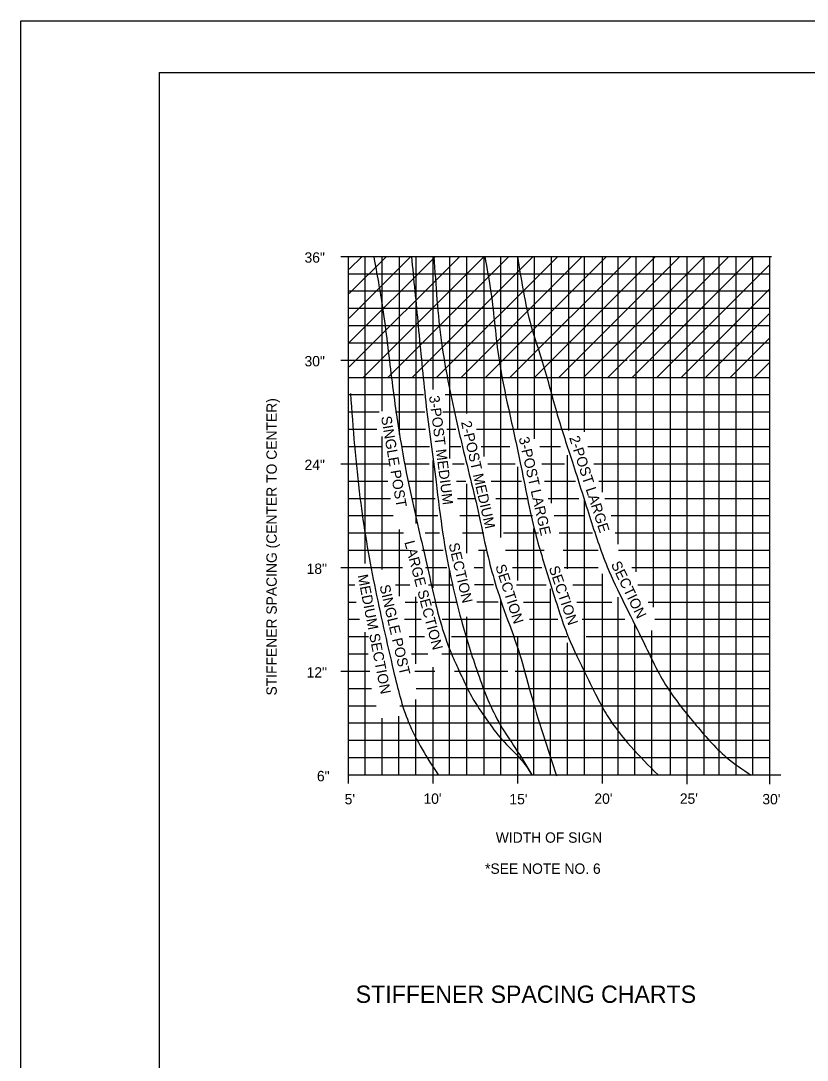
# Model space of a CAD drawing. Extents: x 650495 to 652241, y 298458 to 299646.
# Drawn here: x 650495.3 to 650722.7, y 299344.9 to 299645.6 of the extents above; entities that cross this region are included whole.
import ezdxf

# ---------------------------------------------------------------- set-up
doc = ezdxf.new("R2010")
doc.units = 0
for name, color, linetype in [('1', 7, 'Continuous'), ('2', 7, 'Continuous'), ('3', 7, 'Continuous'), ('PLT-BNDY', 7, 'Continuous')]:
    doc.layers.add(name, color=color, linetype=linetype)

msp = doc.modelspace()

# ---------------------------------------------------------------- linework, layer by layer
at = {"layer": '1'}
for q in [(651321.31, 299630.63), (650535.31, 299066.63)]:
    msp.add_line((650535.31, 299630.63), q, dxfattribs=at)
at = {"layer": '2'}
for p, q in [((650587.82, 299577.45), (650712.44, 299577.45)), ((650590.32, 299573.76), (650594, 299577.45)), ((650590.32, 299566.69), (650601.07, 299577.45)), ((650590.32, 299559.62), (650608.15, 299577.45)), ((650590.32, 299552.55), (650615.22, 299577.45)), ((650590.32, 299545.48), (650622.29, 299577.45)), ((650593.07, 299577.45), (650593.07, 299577.45)), ((650594.36, 299542.45), (650629.36, 299577.45)), ((650601.43, 299542.45), (650636.43, 299577.45)), ((650605.32, 299577.45), (650605.32, 299577.45)), ((650608.5, 299542.45), (650643.5, 299577.45)), ((650615.57, 299542.45), (650650.57, 299577.45)), ((650622.64, 299542.45), (650657.64, 299577.45)), ((650623.69, 299577.45), (650623.69, 299577.45)), ((650629.07, 299577.45), (650629.07, 299577.45)), ((650629.71, 299542.45), (650664.71, 299577.45)), ((650636.78, 299542.45), (650671.78, 299577.45)), ((650643.86, 299542.45), (650678.86, 299577.45)), ((650650.93, 299542.45), (650685.93, 299577.45)), ((650658, 299542.45), (650693, 299577.45)), ((650658.94, 299577.45), (650658.94, 299577.45)), ((650665.07, 299542.45), (650700.07, 299577.45)), ((650672.14, 299542.45), (650707.14, 299577.45)), ((650679.21, 299542.45), (650711.82, 299575.05)), ((650590.32, 299572.45), (650711.82, 299572.45)), ((650605.32, 299572.45), (650605.32, 299572.45)), ((650630.32, 299569.82), (650630.32, 299569.82)), ((650590.32, 299567.45), (650711.82, 299567.45)), ((650686.28, 299542.45), (650711.82, 299567.98)), ((650590.32, 299562.45), (650711.82, 299562.45)), ((650631.44, 299562.45), (650631.44, 299562.45)), ((650693.35, 299542.45), (650711.82, 299560.91)), ((650590.32, 299557.45), (650711.82, 299557.45)), ((650625.32, 299557.45), (650625.32, 299557.45)), ((650662.94, 299557.45), (650662.94, 299557.45)), ((650700.42, 299542.45), (650711.82, 299553.84)), ((650590.32, 299552.45), (650711.82, 299552.45)), ((650587.82, 299547.45), (650670.69, 299547.45)), ((650595.32, 299547.45), (650595.32, 299547.45)), ((650634.57, 299547.45), (650634.57, 299547.45)), ((650671.32, 299547.45), (650711.82, 299547.45)), ((650707.5, 299542.45), (650711.82, 299546.77)), ((650590.32, 299542.45), (650711.82, 299542.45)), ((650607.69, 299542.45), (650607.69, 299542.45)), ((650590.32, 299537.45), (650611.73, 299537.45)), ((650618.07, 299537.45), (650711.82, 299537.45)), ((650590.32, 299532.45), (650598.94, 299532.45)), ((650603.69, 299532.45), (650612.12, 299532.45)), ((650617.38, 299532.45), (650711.82, 299532.45)), ((650590.32, 299527.45), (650598.25, 299527.45)), ((650604.69, 299527.45), (650612.32, 299527.45)), ((650610.32, 299527.45), (650610.32, 299527.45)), ((650618.56, 299527.45), (650621.14, 299527.45)), ((650627.09, 299527.45), (650711.82, 299527.45)), ((650590.32, 299522.45), (650599.64, 299522.45)), ((650605.57, 299522.45), (650613.51, 299522.45)), ((650619.46, 299522.45), (650622.53, 299522.45)), ((650628.47, 299522.45), (650636.69, 299522.45)), ((650645.41, 299522.45), (650651.36, 299522.45)), ((650659.28, 299522.45), (650711.82, 299522.45)), ((650587.82, 299517.45), (650601.94, 299517.45)), ((650606.57, 299517.45), (650613.41, 299517.45)), ((650620.15, 299517.45), (650623.52, 299517.45)), ((650630.35, 299517.45), (650638.32, 299517.45)), ((650646.01, 299517.45), (650652.55, 299517.45)), ((650661.07, 299517.45), (650711.82, 299517.45)), ((650590.32, 299512.45), (650601.42, 299512.45)), ((650607.44, 299512.45), (650614.44, 299512.45)), ((650621.34, 299512.45), (650624.01, 299512.45)), ((650631.35, 299512.45), (650640.07, 299512.45)), ((650645.32, 299512.45), (650645.32, 299512.45)), ((650646.8, 299512.45), (650655.72, 299512.45)), ((650662.46, 299512.45), (650711.82, 299512.45)), ((650590.32, 299507.45), (650602.22, 299507.45)), ((650608.44, 299507.45), (650615.1, 299507.45)), ((650621.64, 299507.45), (650626.59, 299507.45)), ((650632.73, 299507.45), (650641.69, 299507.45)), ((650647.79, 299507.45), (650656.71, 299507.45)), ((650664.24, 299507.45), (650711.82, 299507.45)), ((650590.32, 299502.45), (650603.01, 299502.45)), ((650609.44, 299502.45), (650615.89, 299502.45)), ((650622.23, 299502.45), (650627.78, 299502.45)), ((650633.92, 299502.45), (650643.32, 299502.45)), ((650649.58, 299502.45), (650658.1, 299502.45)), ((650666.02, 299502.45), (650711.82, 299502.45)), ((650590.32, 299497.45), (650605.94, 299497.45)), ((650612.22, 299497.45), (650616.39, 299497.45)), ((650623.02, 299497.45), (650629.17, 299497.45)), ((650634.91, 299497.45), (650645.07, 299497.45)), ((650650.96, 299497.45), (650660.67, 299497.45)), ((650667.21, 299497.45), (650711.82, 299497.45)), ((650590.32, 299492.45), (650606.94, 299492.45)), ((650605.32, 299492.45), (650605.32, 299492.45)), ((650611.32, 299492.45), (650617.47, 299492.45)), ((650627.69, 299492.45), (650630.16, 299492.45)), ((650635.51, 299492.45), (650646.69, 299492.45)), ((650652.15, 299492.45), (650662.26, 299492.45)), ((650668.2, 299492.45), (650711.82, 299492.45)), ((650587.82, 299487.45), (650605.68, 299487.45)), ((650590.32, 299487.45), (650590.32, 299487.45)), ((650612.32, 299487.45), (650618.47, 299487.45)), ((650626.39, 299487.45), (650628.97, 299487.45)), ((650637.49, 299487.45), (650646.01, 299487.45)), ((650646.57, 299487.45), (650646.57, 299487.45)), ((650652.44, 299487.45), (650662.26, 299487.45)), ((650671.97, 299487.45), (650711.82, 299487.45)), ((650590.32, 299482.45), (650591.91, 299482.45)), ((650603.7, 299482.45), (650607.86, 299482.45)), ((650613.19, 299482.45), (650620.15, 299482.45)), ((650632.04, 299482.45), (650626.49, 299482.45)), ((650638.68, 299482.45), (650647.2, 299482.45)), ((650654.93, 299482.45), (650663.64, 299482.45)), ((650673.75, 299482.45), (650711.82, 299482.45)), ((650590.32, 299477.45), (650592.31, 299477.45)), ((650606.48, 299477.45), (650610.07, 299477.45)), ((650614.19, 299477.45), (650621.54, 299477.45)), ((650633.33, 299477.45), (650627.18, 299477.45)), ((650640.66, 299477.45), (650648.39, 299477.45)), ((650656.11, 299477.45), (650666.22, 299477.45)), ((650676.72, 299477.45), (650711.82, 299477.45)), ((650590.32, 299472.45), (650593.3, 299472.45)), ((650606.28, 299472.45), (650611.07, 299472.45)), ((650617.18, 299472.45), (650633.72, 299472.45)), ((650642.44, 299472.45), (650650.57, 299472.45)), ((650657.7, 299472.45), (650669.99, 299472.45)), ((650678.7, 299472.45), (650711.82, 299472.45)), ((650706.69, 299472.45), (650706.69, 299472.45)), ((650590.32, 299467.45), (650595.82, 299467.45)), ((650607.67, 299467.45), (650612.07, 299467.45)), ((650610.32, 299467.45), (650610.32, 299467.45)), ((650619.85, 299467.45), (650653.24, 299467.45)), ((650657.69, 299467.45), (650657.69, 299467.45)), ((650658.79, 299467.45), (650711.82, 299467.45)), ((650590.32, 299462.45), (650595.78, 299462.45)), ((650608.26, 299462.45), (650613.07, 299462.45)), ((650617.07, 299462.45), (650711.82, 299462.45)), ((650587.82, 299457.45), (650596.27, 299457.45)), ((650595.32, 299457.45), (650595.32, 299457.45)), ((650609.25, 299457.45), (650615, 299457.45)), ((650620.74, 299457.45), (650636.19, 299457.45)), ((650638.32, 299457.45), (650711.82, 299457.45)), ((650590.32, 299452.45), (650596.77, 299452.45)), ((650609.65, 299452.45), (650711.82, 299452.45)), ((650590.32, 299447.45), (650598.06, 299447.45)), ((650604.94, 299447.45), (650711.82, 299447.45)), ((650640.32, 299447.45), (650640.32, 299447.45)), ((650684.57, 299447.45), (650684.57, 299447.45)), ((650590.32, 299442.45), (650711.82, 299442.45)), ((650690.32, 299442.45), (650690.32, 299442.45)), ((650590.32, 299437.45), (650711.82, 299437.45)), ((650625.32, 299437.45), (650625.32, 299437.45)), ((650647.94, 299437.45), (650647.94, 299437.45)), ((650685.32, 299437.45), (650685.32, 299437.45)), ((650697.69, 299437.45), (650697.69, 299437.45)), ((650590.32, 299432.45), (650711.82, 299432.45)), ((650605.32, 299432.45), (650605.32, 299432.45)), ((650589.94, 299427.45), (650715.07, 299427.45)), ((650710.32, 299427.45), (650710.32, 299427.45))]:
    msp.add_line(p, q, dxfattribs=at)
for points in [[(650589.94, 299577.45), (650589.94, 299424.95)], [(650594.82, 299577.45), (650594.82, 299488.57)], [(650599.69, 299577.45), (650599.69, 299532.7)], [(650604.69, 299577.45), (650604.69, 299525.95)], [(650609.57, 299577.45), (650609.57, 299500.2)], [(650614.44, 299577.45), (650614.44, 299538.95)], [(650619.32, 299577.45), (650619.32, 299518.93)], [(650624.19, 299577.45), (650624.19, 299532.01)], [(650629.19, 299577.45), (650629.19, 299519.52)], [(650634.07, 299577.45), (650634.07, 299496.14)], [(650638.94, 299577.45), (650638.94, 299527.32)], [(650643.82, 299577.45), (650643.82, 299524.68)], [(650648.69, 299577.45), (650648.69, 299506.05)], [(650653.69, 299577.45), (650653.69, 299527.06)], [(650658.19, 299577.45), (650658.19, 299526.66)], [(650663.44, 299577.45), (650663.44, 299509.22)], [(650667.94, 299577.45), (650667.94, 299494.15)], [(650673.19, 299577.45), (650673.19, 299486.23)], [(650678.19, 299577.45), (650678.19, 299475.92)], [(650683.07, 299577.45), (650683.07, 299427.45)], [(650687.94, 299577.45), (650687.94, 299424.77)], [(650692.82, 299577.45), (650692.82, 299427.45)], [(650697.19, 299577.45), (650697.19, 299427.45)], [(650702.07, 299577.45), (650702.07, 299427.45)], [(650706.94, 299577.45), (650706.94, 299427.45)], [(650711.82, 299577.45), (650711.82, 299424.74)], [(650599.69, 299525.37), (650599.69, 299486.82)], [(650614.44, 299518.43), (650614.44, 299481.57)], [(650653.32, 299519.92), (650653.32, 299487.02)], [(650638.94, 299516.57), (650638.94, 299483.65)], [(650624.19, 299511.6), (650624.19, 299491.58)], [(650658.19, 299507.43), (650658.19, 299427.45)], [(650604.69, 299498.42), (650604.69, 299479.19)], [(650643.57, 299498.71), (650643.57, 299427.45)], [(650629.19, 299492.57), (650629.19, 299427.45)], [(650619.19, 299487.02), (650619.19, 299427.45)], [(650663.44, 299485.63), (650663.44, 299424.95)], [(650648.44, 299481.27), (650648.44, 299427.45)], [(650609.44, 299478.95), (650609.44, 299459.57)], [(650634.07, 299477.9), (650634.07, 299427.45)], [(650667.94, 299478.89), (650667.94, 299427.45)], [(650624.19, 299473.14), (650624.19, 299427.45)], [(650672.82, 299470.96), (650672.82, 299427.45)], [(650677.69, 299469.18), (650677.69, 299427.45)], [(650594.82, 299468.69), (650594.82, 299427.45)], [(650638.94, 299467.6), (650638.94, 299424.95)], [(650653.32, 299465.61), (650653.32, 299427.45)], [(650614.44, 299458.58), (650614.44, 299424.95)], [(650609.44, 299449.26), (650609.44, 299427.45)], [(650599.69, 299443.81), (650599.69, 299427.45)], [(650604.57, 299444.41), (650604.57, 299427.45)]]:
    msp.add_lwpolyline(points, dxfattribs=at)
for points in [[(650597.36, 299577.45), (650599.94, 299562.53), (650602.51, 299542.32), (650605.49, 299522.1), (650608.26, 299507.83), (650610.64, 299497.33), (650613.02, 299487.02), (650615.2, 299477.31), (650616.58, 299471.96), (650619.95, 299462.24), (650621.93, 299457.88), (650624.31, 299452.73), (650627.09, 299447.78), (650630.06, 299443.41), (650634.42, 299437.67), (650639.77, 299432.12), (650643.14, 299427.45)], [(650608.26, 299577.45), (650610.24, 299557.38), (650612.42, 299535.38), (650615.39, 299512.19), (650617.38, 299497.13), (650622.73, 299472.15), (650627.48, 299456.89), (650634.02, 299441.83), (650638.38, 299435.09), (650643.14, 299427.45)], [(650614.8, 299577.45), (650616.98, 299552.45), (650621.14, 299530.62), (650622.73, 299523.69), (650627.88, 299502.28), (650630.45, 299490.49), (650632.83, 299481.87), (650636.6, 299470.96), (650639.57, 299462.44), (650642.74, 299451.14), (650650.27, 299427.16)], [(650629.46, 299577.45), (650631.25, 299567.09), (650633.62, 299547.47), (650636.4, 299533.2), (650639.77, 299517.74), (650644.13, 299497.33), (650648.49, 299482.66), (650653.64, 299467.4), (650658.79, 299456.3), (650661.96, 299449.96), (650664.93, 299444.6), (650679.6, 299427.45)], [(650638.97, 299577.45), (650642.94, 299557.18), (650646.11, 299547.07), (650650.47, 299531.61), (650654.83, 299517.94), (650659.78, 299502.28), (650664.93, 299487.61), (650674.84, 299467), (650681.78, 299453.52), (650690.1, 299442.42), (650699.41, 299432.51), (650706.54, 299427.36)], [(650590.63, 299537.76), (650593.4, 299507.63), (650597.56, 299482.46), (650603.11, 299457.49), (650607.47, 299442.62), (650615.99, 299427.45)]]:
    msp.add_spline(points, degree=3, dxfattribs=at)
at = {"layer": 'PLT-BNDY'}
msp.add_lwpolyline([(650495.31, 299645.63), (651336.31, 299645.63), (651336.31, 299051.63), (650495.31, 299051.63)], close=True, dxfattribs=at)

# ---------------------------------------------------------------- texts
at = {"layer": '2'}
for s, height, rotation, p in [('STIFFENER SPACING (CENTER TO CENTER)', 3, 90, (650569.34, 299450.4)), ('3-POST MEDIUM', 2.9992, 277.2906, (650613.36, 299537.02)), ('SINGLE POST', 3, 279.7906, (650599.47, 299531.02)), ('2-POST MEDIUM', 3, 282.7906, (650622.6, 299529.5)), ('3-POST LARGE', 3, 282.7906, (650639.29, 299524.91)), ('2-POST LARGE', 3, 287.7906, (650653.87, 299525.01)), ('LARGE SECTION', 3, 284.7906, (650606.22, 299494.79)), ('SECTION', 2.999, 283.2906, (650619.01, 299494.23)), ('SECTION', 3, 287.7906, (650632.52, 299487.83)), ('SECTION', 3, 288.7906, (650647.97, 299487.34)), ('SECTION', 3, 295.7906, (650665.9, 299488.41)), ('MEDIUM SECTION', 3, 281.0612, (650592.7, 299485.15)), ('SINGLE POST', 3, 283.0612, (650599.03, 299482.12))]:
    msp.add_text(s, height=height, rotation=rotation, dxfattribs=at).set_placement(p)
for s, height, p in [('WIDTH OF SIGN', 3, (650632.67, 299407.8)), ('*SEE NOTE NO. 6', 3, (650629.57, 299398.8)), ('STIFFENER SPACING CHARTS', 5, (650592.16, 299361.47))]:
    msp.add_text(s, height=height, dxfattribs=at).set_placement(p)
at = {"layer": '3'}
for s, p in [('36"', (650577.36, 299575.64)), ('30"', (650577.36, 299545.64)), ('24"', (650577.36, 299515.64)), ('18"', (650577.97, 299485.58)), ('12"', (650577.97, 299455.58)), ('6"', (650580.95, 299425.58)), ("5'", (650588.97, 299418.91)), ("10'", (650611.76, 299419.06)), ("15'", (650636.62, 299418.91)), ("20'", (650661.19, 299419.06)), ("25'", (650685.9, 299419.06)), ("30'", (650709.76, 299418.91))]:
    msp.add_text(s, height=3, dxfattribs=at).set_placement(p)

doc.saveas('drawing.dxf')
